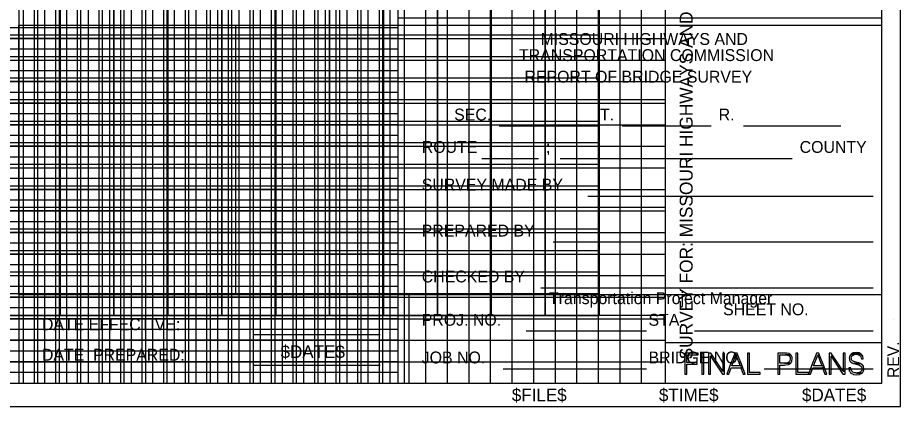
# Model space of a CAD drawing. Extents: x 0 to 31.6, y 0 to 20.8.
# Drawn here: x 23.41 to 31.6, y 0 to 3.61 of the extents above; entities that cross this region are included whole.
import ezdxf

# ---------------------------------------------------------------- set-up
doc = ezdxf.new("R2010")
doc.units = 0
for name, color, linetype in [('Border-Border', 7, 'Continuous'), ('Border-Bridge survey title block', 7, 'Continuous'), ('Border-Bridge xsection major grid lines', 7, 'Continuous'), ('Border-Bridge xsection minor grid lines', 7, 'Continuous'), ('Border-Construction Final Plans Stamp', 7, 'Continuous'), ('Border-Date stamp', 7, 'Continuous'), ('Border-File stamp', 7, 'Continuous'), ('Border-Full plan shape', 7, 'Continuous'), ('Border-Full profile major grid lines', 7, 'Continuous'), ('Border-Full profile minor grid lines', 7, 'Continuous'), ('Border-Full profile shape', 7, 'Continuous'), ('Border-Full xsection major grid lines', 7, 'Continuous'), ('Border-Full xsection minor grid lines', 7, 'Continuous'), ('Border-Plan bottom shape', 7, 'Continuous'), ('Border-Plan-profile major grid lines', 7, 'Continuous'), ('Border-Plan-profile minor grid lines', 7, 'Continuous'), ('Border-Plotting block', 7, 'Continuous'), ('Border-Profile bottom shape', 7, 'Continuous'), ('Border-Revision note', 7, 'Continuous'), ('Border-Time stamp', 7, 'Continuous'), ('Border-Title block - Final Plans Consultant Manual Seal', 7, 'Continuous'), ('Border-Title block - Final Plans Electronic Seal', 7, 'Continuous'), ('Border-Title block - Location Survey Electronic Seal', 7, 'Continuous'), ('Border-Title block - Standard Plans Electronic Seal', 7, 'Continuous'), ('Border-Xsection shape', 7, 'Continuous')]:
    doc.layers.add(name, color=color, linetype=linetype)

msp = doc.modelspace()

# ---------------------------------------------------------------- linework, layer by layer
at = {"layer": 'Border-Border'}
for p, q in [((31.425, 20.5875), (31.425, 0.2125)), ((31.425, 0.2125), (0.175, 0.2125)), ((31.5999, 0), (31.5999, 0))]:
    msp.add_line(p, q, dxfattribs=at)
at = {"layer": 'Border-Bridge survey title block'}
for p, q in [((26.9414, 3.6031), (31.4249, 3.6031)), ((27.8783, 2.6015), (28.7934, 2.6015)), ((29.02, 2.6015), (29.8454, 2.6015)), ((30.1465, 2.6015), (31.047, 2.6015)), ((27.7184, 2.3007), (28.2439, 2.3007)), ((28.4439, 2.3007), (30.5966, 2.3007)), ((28.7003, 1.9511), (31.3478, 1.9511)), ((28.3806, 1.5251), (31.3478, 1.5251)), ((28.2664, 1.0991), (31.3478, 1.0991)), ((28.1294, 0.6991), (29.2454, 0.6991)), ((29.6898, 0.6991), (31.3478, 0.6991)), ((27.9164, 0.3479), (29.2454, 0.3479)), ((30.3368, 0.3479), (31.3478, 0.3479))]:
    msp.add_line(p, q, dxfattribs=at)
msp.add_lwpolyline([(26.9414, 0.2125), (26.9414, 4.2047), (31.4249, 4.2047)], dxfattribs=at)
at = {"layer": 'Border-Bridge xsection major grid lines'}
for p, q in [((23.665, 0.2125), (23.665, 20.5875)), ((24.665, 0.2125), (24.665, 20.5875)), ((25.6649, 0.2125), (25.6649, 20.5875)), ((26.6649, 0.2125), (26.6649, 20.5875)), ((0.175, 3.2125), (26.9415, 3.2125)), ((0.175, 2.2125), (26.9415, 2.2125)), ((0.175, 1.2125), (26.9415, 1.2125))]:
    msp.add_line(p, q, dxfattribs=at)
at = {"layer": 'Border-Bridge xsection minor grid lines'}
for p, q in [((23.465, 20.5875), (23.465, 0.2125)), ((23.565, 20.5875), (23.565, 0.2125)), ((23.765, 20.5875), (23.765, 0.2125)), ((23.865, 20.5875), (23.865, 0.2125)), ((23.965, 20.5875), (23.965, 0.2125)), ((24.065, 20.5875), (24.065, 0.2125)), ((24.165, 20.5875), (24.165, 0.2125)), ((24.265, 20.5875), (24.265, 0.2125)), ((24.365, 20.5875), (24.365, 0.2125)), ((24.465, 20.5875), (24.465, 0.2125)), ((24.565, 20.5875), (24.565, 0.2125)), ((24.765, 20.5875), (24.765, 0.2125)), ((24.865, 20.5875), (24.865, 0.2125)), ((24.965, 20.5875), (24.965, 0.2125)), ((25.0649, 20.5875), (25.0649, 0.2125)), ((25.1649, 20.5875), (25.1649, 0.2125)), ((25.2649, 20.5875), (25.2649, 0.2125)), ((25.3649, 20.5875), (25.3649, 0.2125)), ((25.4649, 20.5875), (25.4649, 0.2125)), ((25.5649, 20.5875), (25.5649, 0.2125)), ((25.7649, 20.5875), (25.7649, 0.2125)), ((25.8649, 20.5875), (25.8649, 0.2125)), ((25.9649, 20.5875), (25.9649, 0.2125)), ((26.0649, 20.5875), (26.0649, 0.2125)), ((26.1649, 20.5875), (26.1649, 0.2125)), ((26.2649, 20.5875), (26.2649, 0.2125)), ((26.3649, 20.5875), (26.3649, 0.2125)), ((26.4649, 20.5875), (26.4649, 0.2125)), ((26.5649, 20.5875), (26.5649, 0.2125)), ((26.7649, 20.5875), (26.7649, 0.2125)), ((26.8649, 20.5875), (26.8649, 0.2125)), ((26.9415, 3.5125), (0.175, 3.5125)), ((26.9415, 3.4125), (0.175, 3.4125)), ((26.9415, 3.3125), (0.175, 3.3125)), ((26.9415, 3.1125), (0.175, 3.1125)), ((26.9415, 3.0125), (0.175, 3.0125)), ((26.9415, 2.9125), (0.175, 2.9125)), ((26.9415, 2.8125), (0.175, 2.8125)), ((26.9415, 2.7125), (0.175, 2.7125)), ((26.9415, 2.6125), (0.175, 2.6125)), ((26.9415, 2.5125), (0.175, 2.5125)), ((26.9415, 2.4125), (0.175, 2.4125)), ((26.9415, 2.3125), (0.175, 2.3125)), ((26.9415, 2.1125), (0.175, 2.1125)), ((26.9415, 2.0125), (0.175, 2.0125)), ((26.9415, 1.9125), (0.175, 1.9125)), ((26.9415, 1.8125), (0.175, 1.8125)), ((26.9415, 1.7125), (0.175, 1.7125)), ((26.9415, 1.6125), (0.175, 1.6125)), ((26.9415, 1.5125), (0.175, 1.5125)), ((26.9415, 1.4125), (0.175, 1.4125)), ((26.9415, 1.3125), (0.175, 1.3125)), ((26.9415, 1.1125), (0.175, 1.1125)), ((26.9415, 1.0125), (0.175, 1.0125)), ((26.9415, 0.9125), (0.175, 0.9125)), ((26.9415, 0.8125), (0.175, 0.8125)), ((26.9415, 0.7125), (0.175, 0.7125)), ((26.9415, 0.6125), (0.175, 0.6125)), ((26.9415, 0.5125), (0.175, 0.5125)), ((26.9415, 0.4125), (0.175, 0.4125)), ((26.9415, 0.3125), (0.175, 0.3125))]:
    msp.add_line(p, q, dxfattribs=at)
at = {"layer": 'Border-Construction Final Plans Stamp'}
msp.add_line((29.4171, 0.5925), (31.4249, 0.5925), dxfattribs=at)
for points in [[(29.6017, 0.3913), (29.6017, 0.2983), (29.6199, 0.2983), (29.6199, 0.3913), (29.716, 0.3913), (29.716, 0.4074), (29.6199, 0.4074), (29.6199, 0.4783), (29.7258, 0.4783), (29.7258, 0.4943), (29.6017, 0.4943), (29.6017, 0.4783), (29.6017, 0.4074)], [(29.758, 0.4943), (29.758, 0.2983), (29.7765, 0.2983), (29.7765, 0.4943)], [(29.8215, 0.3262), (29.8215, 0.2983), (29.8392, 0.2983), (29.8392, 0.3262), (29.8392, 0.4665), (29.8596, 0.4665), (29.8414, 0.4943), (29.8215, 0.4943), (29.8215, 0.4665)], [(29.952, 0.4943), (29.952, 0.3262), (29.9697, 0.3262), (29.9697, 0.4943)], [(30.0132, 0.3587), (29.9903, 0.2983), (30.009, 0.2983), (30.0315, 0.3587), (30.1377, 0.3587), (30.1317, 0.3744), (30.0373, 0.3744), (30.0754, 0.4754), (30.0933, 0.4754), (30.0862, 0.4943), (30.0647, 0.4943), (30.0575, 0.4754), (30.0192, 0.3744)], [(30.1813, 0.3143), (30.1813, 0.2983), (30.3, 0.2983), (30.3, 0.3143), (30.1998, 0.3143), (30.1998, 0.4943), (30.1813, 0.4943)], [(30.4647, 0.3834), (30.4647, 0.2983), (30.4828, 0.2983), (30.4828, 0.3834), (30.5245, 0.3834), (30.5391, 0.3839), (30.5619, 0.3879), (30.5812, 0.3987), (30.582, 0.3998), (30.4828, 0.3998), (30.4828, 0.3999), (30.4828, 0.4015), (30.4828, 0.4086), (30.4828, 0.4168), (30.4828, 0.4228), (30.4828, 0.4394), (30.4828, 0.4396), (30.4828, 0.4557), (30.4828, 0.4598), (30.4828, 0.4682), (30.4828, 0.4757), (30.4828, 0.4774), (30.4828, 0.4779), (30.4828, 0.4783), (30.5834, 0.4783), (30.5671, 0.4893), (30.5474, 0.4937), (30.5333, 0.4943), (30.4647, 0.4943), (30.4647, 0.4937), (30.4647, 0.4893), (30.4647, 0.4783), (30.4647, 0.4779), (30.4647, 0.4774), (30.4647, 0.4757), (30.4647, 0.4682), (30.4647, 0.4598), (30.4647, 0.4557), (30.4647, 0.4396), (30.4647, 0.4394), (30.4647, 0.4228), (30.4647, 0.4168), (30.4647, 0.4086), (30.4647, 0.4015), (30.4647, 0.3999), (30.4647, 0.3998), (30.4647, 0.3987), (30.4647, 0.3879), (30.4647, 0.3839)], [(30.6295, 0.3143), (30.6295, 0.2983), (30.7482, 0.2983), (30.7482, 0.3143), (30.648, 0.3143), (30.648, 0.4943), (30.6295, 0.4943)], [(30.7711, 0.3587), (30.7482, 0.2983), (30.7669, 0.2983), (30.7894, 0.3587), (30.8956, 0.3587), (30.8896, 0.3744), (30.7952, 0.3744), (30.8333, 0.4754), (30.8512, 0.4754), (30.8441, 0.4943), (30.8226, 0.4943), (30.8154, 0.4754), (30.7771, 0.3744)], [(30.9392, 0.3262), (30.9392, 0.2983), (30.9569, 0.2983), (30.9569, 0.3262), (30.9569, 0.4665), (30.9774, 0.4665), (30.9591, 0.4943), (30.9392, 0.4943), (30.9392, 0.4665)], [(31.0697, 0.4943), (31.0697, 0.3262), (31.0874, 0.3262), (31.0874, 0.4943)], [(31.1443, 0.4851), (31.1434, 0.4846), (31.2378, 0.4846), (31.2374, 0.4851), (31.2175, 0.4957), (31.2149, 0.4961), (31.1643, 0.4961), (31.1636, 0.4957)], [(31.1906, 0.4997), (31.1643, 0.4961), (31.2149, 0.4961)], [(29.9314, 0.3262), (29.9498, 0.2983), (29.9697, 0.2983), (29.9697, 0.3262), (29.952, 0.3262), (29.8597, 0.4665), (29.8392, 0.4665)], [(30.0754, 0.4754), (30.1135, 0.3744), (30.1317, 0.3744), (30.0934, 0.4754)], [(30.5324, 0.4783), (30.5394, 0.4779), (30.5839, 0.4779), (30.5834, 0.4783)], [(30.5657, 0.4086), (30.5497, 0.4015), (30.5831, 0.4015), (30.588, 0.4086), (30.5936, 0.4168), (30.5947, 0.4228), (30.5946, 0.4228), (30.5976, 0.4394), (30.5976, 0.4396), (30.5954, 0.4557), (30.5949, 0.4598), (30.59, 0.4682), (30.5856, 0.4757), (30.5846, 0.4774), (30.5839, 0.4779), (30.5394, 0.4779), (30.5428, 0.4774), (30.5544, 0.4757), (30.5686, 0.4682), (30.5741, 0.4598), (30.5767, 0.4557), (30.5791, 0.4396), (30.5791, 0.4394), (30.5762, 0.4228), (30.5718, 0.4168)], [(30.8333, 0.4754), (30.8714, 0.3744), (30.8896, 0.3744), (30.8513, 0.4754)], [(31.0492, 0.3262), (31.0675, 0.2983), (31.0874, 0.2983), (31.0874, 0.3262), (31.0697, 0.3262), (30.9774, 0.4665), (30.9569, 0.4665)], [(31.1654, 0.3978), (31.1677, 0.3969), (31.2311, 0.3969), (31.2296, 0.3978), (31.2145, 0.4031), (31.2144, 0.4031), (31.2128, 0.4037), (31.2007, 0.4071), (31.1779, 0.4129), (31.1752, 0.4137), (31.1671, 0.4161), (31.1548, 0.4228), (31.1503, 0.4286), (31.1471, 0.4328), (31.1457, 0.4397), (31.1445, 0.4462), (31.1445, 0.4464), (31.1445, 0.4469), (31.1446, 0.4474), (31.1467, 0.4596), (31.1469, 0.4611), (31.151, 0.4668), (31.1515, 0.4674), (31.1515, 0.4674), (31.1551, 0.4724), (31.1555, 0.473), (31.1703, 0.481), (31.1709, 0.4814), (31.1897, 0.4836), (31.2385, 0.4836), (31.2378, 0.4846), (31.1434, 0.4846), (31.1427, 0.4836), (31.141, 0.4814), (31.1408, 0.481), (31.135, 0.473), (31.1346, 0.4724), (31.1309, 0.4674), (31.1305, 0.4668), (31.1294, 0.4611), (31.1291, 0.4596), (31.1267, 0.4474), (31.1266, 0.4469), (31.1267, 0.4464), (31.1267, 0.4462), (31.1276, 0.4397), (31.1286, 0.4328), (31.1292, 0.4286), (31.1325, 0.4228), (31.1365, 0.4161), (31.1379, 0.4137), (31.139, 0.4129), (31.1464, 0.4071), (31.1508, 0.4037), (31.1515, 0.4031)], [(31.238, 0.4462), (31.2384, 0.4397), (31.2565, 0.4397), (31.2561, 0.4462), (31.2561, 0.4464), (31.2561, 0.4469), (31.2561, 0.4474), (31.2528, 0.4596), (31.2528, 0.4596), (31.2524, 0.4611), (31.2509, 0.4668), (31.2507, 0.4674), (31.2469, 0.4724), (31.2465, 0.473), (31.2404, 0.481), (31.2402, 0.4814), (31.2402, 0.4814), (31.2385, 0.4836), (31.1897, 0.4836), (31.2063, 0.4814), (31.2086, 0.481), (31.2239, 0.473), (31.225, 0.4724), (31.2287, 0.4674), (31.2291, 0.4668), (31.2332, 0.4611), (31.2343, 0.4596), (31.2377, 0.4474), (31.2378, 0.4469), (31.2379, 0.4464)], [(30.1194, 0.3587), (30.1418, 0.2983), (30.1606, 0.2983), (30.1377, 0.3587)], [(30.5323, 0.3999), (30.5248, 0.3998), (30.582, 0.3998), (30.582, 0.3999)], [(30.5496, 0.4015), (30.5324, 0.3999), (30.582, 0.3999), (30.5831, 0.4015)], [(30.8772, 0.3587), (30.8997, 0.2983), (30.9185, 0.2983), (30.8956, 0.3587)], [(31.1647, 0.2968), (31.1947, 0.293), (31.2202, 0.2968), (31.224, 0.2974), (31.2444, 0.309), (31.195, 0.309), (31.1924, 0.3093), (31.186, 0.3101), (31.1753, 0.3113), (31.174, 0.3119), (31.1585, 0.3186), (31.1553, 0.3221), (31.1498, 0.3279), (31.1498, 0.3279), (31.1471, 0.3308), (31.1459, 0.3322), (31.1442, 0.337), (31.1408, 0.3468), (31.1404, 0.3502), (31.1403, 0.3517), (31.1398, 0.3577), (31.1217, 0.3577), (31.1219, 0.3517), (31.122, 0.3502), (31.1227, 0.3468), (31.1246, 0.337), (31.1255, 0.3322), (31.1258, 0.3308), (31.1278, 0.3279), (31.1319, 0.3221), (31.1343, 0.3186), (31.139, 0.3119), (31.1395, 0.3113), (31.1403, 0.3101), (31.1409, 0.3093), (31.1415, 0.309), (31.1636, 0.2974)], [(31.1974, 0.3093), (31.195, 0.309), (31.2444, 0.309), (31.2449, 0.3093), (31.2462, 0.3101), (31.2471, 0.3113), (31.2475, 0.3119), (31.2521, 0.3186), (31.2545, 0.3221), (31.2585, 0.3279), (31.2589, 0.3308), (31.2589, 0.3308), (31.2591, 0.3322), (31.2598, 0.337), (31.2613, 0.3468), (31.2618, 0.3502), (31.2621, 0.3517), (31.2592, 0.3661), (31.2579, 0.3723), (31.2541, 0.3771), (31.2484, 0.3846), (31.2458, 0.3879), (31.2439, 0.3891), (31.2439, 0.3891), (31.2361, 0.3938), (31.2311, 0.3969), (31.1677, 0.3969), (31.1796, 0.3938), (31.1982, 0.3891), (31.2022, 0.3879), (31.2142, 0.3846), (31.2302, 0.3771), (31.2346, 0.3723), (31.2402, 0.3661), (31.2438, 0.3517), (31.2437, 0.3502), (31.2434, 0.3468), (31.2427, 0.337), (31.2399, 0.3322), (31.2391, 0.3308), (31.2374, 0.3279), (31.2341, 0.3221), (31.2281, 0.3186), (31.2166, 0.3119), (31.2124, 0.3113), (31.203, 0.3101)]]:
    msp.add_lwpolyline(points, close=True, dxfattribs=at)
at = {"layer": 'Border-Full plan shape'}
msp.add_lwpolyline([(0.8061, 19.9564), (28.8061, 19.9564), (28.8061, 0.8436), (0.8061, 0.8436)], close=True, dxfattribs=at)
at = {"layer": 'Border-Full profile major grid lines'}
for p, q in [((23.8061, 19.8436), (23.8061, 0.8436)), ((24.8061, 19.8436), (24.8061, 0.8436)), ((25.8061, 19.8436), (25.8061, 0.8436)), ((26.8061, 19.8436), (26.8061, 0.8436)), ((27.8061, 19.8436), (27.8061, 0.8436)), ((28.8061, 19.8436), (28.8061, 0.8436)), ((29.4171, 2.8436), (0.175, 2.8436)), ((29.4171, 1.8436), (0.175, 1.8436)), ((29.4171, 0.8436), (0.175, 0.8436))]:
    msp.add_line(p, q, dxfattribs=at)
at = {"layer": 'Border-Full profile minor grid lines'}
for p, q in [((24.3061, 19.8436), (24.3061, 0.8436)), ((25.3061, 19.8436), (25.3061, 0.8436)), ((26.3061, 19.8436), (26.3061, 0.8436)), ((27.3061, 19.8436), (27.3061, 0.8436)), ((28.3061, 19.8436), (28.3061, 0.8436)), ((28.8061, 3.4436), (0.8061, 3.4436)), ((28.8061, 3.2436), (0.8061, 3.2436)), ((28.8061, 3.0436), (0.8061, 3.0436)), ((28.8061, 2.6436), (0.8061, 2.6436)), ((28.8061, 2.4436), (0.8061, 2.4436)), ((28.8061, 2.2436), (0.8061, 2.2436)), ((28.8061, 2.0436), (0.8061, 2.0436)), ((28.8061, 1.6436), (0.8061, 1.6436)), ((28.8061, 1.4436), (0.8061, 1.4436)), ((28.8061, 1.2436), (0.8061, 1.2436)), ((28.8061, 1.0436), (0.8061, 1.0436))]:
    msp.add_line(p, q, dxfattribs=at)
at = {"layer": 'Border-Full profile shape'}
msp.add_lwpolyline([(0.8061, 19.9564), (28.8061, 19.9564), (28.8061, 0.8436), (0.8061, 0.8436)], close=True, dxfattribs=at)
at = {"layer": 'Border-Full xsection major grid lines'}
for p, q in [((23.8, 0.2125), (23.8, 20.5875)), ((24.8, 0.2125), (24.8, 20.5875)), ((25.7999, 0.2125), (25.7999, 20.5875)), ((26.7999, 0.2125), (26.7999, 20.5875)), ((27.7999, 0.2125), (27.7999, 20.5875)), ((28.7999, 0.2125), (28.7999, 20.5875)), ((0.175, 3.2125), (29.4171, 3.2125)), ((0.175, 2.2125), (29.4171, 2.2125)), ((0.175, 1.2125), (29.4171, 1.2125))]:
    msp.add_line(p, q, dxfattribs=at)
at = {"layer": 'Border-Full xsection minor grid lines'}
for p, q in [((23.6, 0.2125), (23.6, 20.5875)), ((24, 0.2125), (24, 20.5875)), ((24.2, 0.2125), (24.2, 20.5875)), ((24.4, 0.2125), (24.4, 20.5875)), ((24.6, 0.2125), (24.6, 20.5875)), ((24.9999, 0.2125), (24.9999, 20.5875)), ((25.1999, 0.2125), (25.1999, 20.5875)), ((25.3999, 0.2125), (25.3999, 20.5875)), ((25.5999, 0.2125), (25.5999, 20.5875)), ((25.9999, 0.2125), (25.9999, 20.5875)), ((26.1999, 0.2125), (26.1999, 20.5875)), ((26.3999, 0.2125), (26.3999, 20.5875)), ((26.5999, 0.2125), (26.5999, 20.5875)), ((26.9999, 0.2125), (26.9999, 20.5875)), ((27.1999, 0.2125), (27.1999, 20.5875)), ((27.3999, 0.2125), (27.3999, 20.5875)), ((27.5999, 0.2125), (27.5999, 20.5875)), ((27.9999, 0.2125), (27.9999, 20.5875)), ((28.1999, 0.2125), (28.1999, 20.5875)), ((28.3999, 0.2125), (28.3999, 20.5875)), ((28.5999, 0.2125), (28.5999, 20.5875)), ((28.9999, 0.2125), (28.9999, 20.5875)), ((29.1999, 0.2125), (29.1999, 20.5875)), ((0.175, 3.4125), (29.4171, 3.4125)), ((0.175, 3.0125), (29.4171, 3.0125)), ((0.175, 2.8125), (29.4171, 2.8125)), ((0.175, 2.6125), (29.4171, 2.6125)), ((0.175, 2.4125), (29.4171, 2.4125)), ((0.175, 2.0125), (29.4171, 2.0125)), ((0.175, 1.8125), (29.4171, 1.8125)), ((0.175, 1.6125), (29.4171, 1.6125)), ((0.175, 1.4125), (29.4171, 1.4125)), ((0.175, 1.0125), (29.4171, 1.0125)), ((0.175, 0.8125), (29.4171, 0.8125)), ((0.175, 0.6125), (29.4171, 0.6125)), ((0.175, 0.4125), (29.4171, 0.4125))]:
    msp.add_line(p, q, dxfattribs=at)
at = {"layer": 'Border-Plan bottom shape'}
msp.add_lwpolyline([(0.8061, 10.3253), (28.8061, 10.3253), (28.8061, 0.8436), (0.8061, 0.8436)], close=True, dxfattribs=at)
at = {"layer": 'Border-Plan-profile major grid lines'}
for p, q in [((23.8061, 0.8436), (23.8061, 9.8436)), ((24.8061, 0.8436), (24.8061, 9.8436)), ((25.8061, 0.8436), (25.8061, 9.8436)), ((26.8061, 0.8436), (26.8061, 9.8436)), ((27.8061, 0.8436), (27.8061, 9.8436)), ((28.8061, 0.8436), (28.8061, 9.8436)), ((29.4233, 2.8436), (0.1811, 2.8436)), ((29.4233, 1.8436), (0.1811, 1.8436)), ((29.4233, 0.8436), (0.1811, 0.8436))]:
    msp.add_line(p, q, dxfattribs=at)
at = {"layer": 'Border-Plan-profile minor grid lines'}
for p, q in [((24.3061, 0.8436), (24.3061, 9.8436)), ((25.3061, 0.8436), (25.3061, 9.8436)), ((26.3061, 0.8436), (26.3061, 9.8436)), ((27.3061, 0.8436), (27.3061, 9.8436)), ((28.3061, 0.8436), (28.3061, 9.8436)), ((28.8061, 3.4436), (0.8061, 3.4436)), ((28.8061, 3.2436), (0.8061, 3.2436)), ((28.8061, 3.0436), (0.8061, 3.0436)), ((28.8061, 2.6436), (0.8061, 2.6436)), ((28.8061, 2.4436), (0.8061, 2.4436)), ((28.8061, 2.2436), (0.8061, 2.2436)), ((28.8061, 2.0436), (0.8061, 2.0436)), ((28.8061, 1.6436), (0.8061, 1.6436)), ((28.8061, 1.4436), (0.8061, 1.4436)), ((28.8061, 1.2436), (0.8061, 1.2436)), ((28.8061, 1.0436), (0.8061, 1.0436))]:
    msp.add_line(p, q, dxfattribs=at)
at = {"layer": 'Border-Plotting block'}
msp.add_lwpolyline([(0, 0), (31.5999, 0), (31.5999, 20.8), (0, 20.8)], close=True, dxfattribs=at)
at = {"layer": 'Border-Profile bottom shape'}
msp.add_lwpolyline([(0.8061, 0.8436), (28.8061, 0.8436), (28.8061, 9.8436), (0.8061, 9.8436)], close=True, dxfattribs=at)
at = {"layer": 'Border-Revision note'}
msp.add_line((31.5347, 0.8092), (31.5347, 0.8092), dxfattribs=at)
at = {"layer": 'Border-Title block - Final Plans Consultant Manual Seal'}
msp.add_line((29.4171, 20.5875), (29.4171, 0.2125), dxfattribs=at)
at = {"layer": 'Border-Title block - Final Plans Electronic Seal'}
msp.add_line((29.4171, 20.5875), (29.4171, 0.2125), dxfattribs=at)
at = {"layer": 'Border-Title block - Location Survey Electronic Seal'}
msp.add_line((29.4171, 20.5875), (29.4171, 0.2125), dxfattribs=at)
at = {"layer": 'Border-Title block - Standard Plans Electronic Seal'}
for p, q in [((23.4249, 4.8718), (23.4249, 0.2125)), ((23.4249, 3.5375), (31.425, 3.5375)), ((25.4328, 3.5375), (25.4328, 1.0375)), ((23.4249, 1.0375), (31.425, 1.0375)), ((27.0397, 1.0375), (27.0397, 0.2125)), ((29.4171, 1.0375), (29.4171, 0.2125)), ((25.6068, 0.6651), (26.7737, 0.6651)), ((25.6068, 0.3818), (26.7737, 0.3818))]:
    msp.add_line(p, q, dxfattribs=at)
msp.add_lwpolyline([(23.4249, 3.5375), (25.4328, 3.5375), (25.4328, 1.0375), (23.4249, 1.0375)], close=True, dxfattribs=at)
at = {"layer": 'Border-Xsection shape'}
msp.add_lwpolyline([(29.4171, 0.2125), (0.175, 0.2125), (0.175, 20.5875), (29.4171, 20.5875)], close=True, dxfattribs=at)

# ---------------------------------------------------------------- texts
at = {"layer": 'Border-Bridge survey title block'}
for s, height, p in [('MISSOURI HIGHWAYS AND', 0.110166, (28.2628, 3.3527)), ('TRANSPORTATION COMMISSION', 0.110192, (28.0628, 3.2031)), ('REPORT OF BRIDGE SURVEY', 0.110192, (28.1131, 3.0031)), ('SEC.', 0.11019, (27.4612, 2.6518)), ('T.', 0.11019, (28.8139, 2.6518)), ('R.', 0.11019, (29.9147, 2.6518)), ('ROUTE', 0.11019, (27.1604, 2.3511)), ('COUNTY', 0.11019, (30.6659, 2.3511)), (';', 0.1102, (28.3131, 2.3511)), ('SURVEY MADE BY', 0.110192, (27.1604, 2.0015)), ('PREPARED BY', 0.110166, (27.1604, 1.5755)), ('CHECKED BY', 0.11019, (27.1604, 1.1495)), ('Transportation Project Manager', 0.110166, (28.3409, 0.948)), ('PROJ. NO.', 0.11019, (27.1604, 0.7479)), ('STA.', 0.11019, (29.2643, 0.7479)), ('JOB NO.', 0.11019, (27.1604, 0.3983)), ('BRIDGE NO.', 0.11019, (29.2643, 0.3983))]:
    msp.add_text(s, height=height, dxfattribs=at).set_placement(p)
at = {"layer": 'Border-Date stamp'}
msp.add_text('$DATE$', height=0.11811, dxfattribs=at).set_placement((30.6876, 0.0472))
at = {"layer": 'Border-File stamp'}
msp.add_text('$FILE$', height=0.11811, dxfattribs=at).set_placement((27.9962, 0.0472))
at = {"layer": 'Border-Revision note'}
msp.add_text('REV.', height=0.10827, rotation=90, dxfattribs=at).set_placement((31.5888, 0.263))
at = {"layer": 'Border-Time stamp'}
msp.add_text('$TIME$', height=0.11811, dxfattribs=at).set_placement((29.3609, 0.0472))
at = {"layer": 'Border-Title block - Location Survey Electronic Seal'}
msp.add_text('SURVEY FOR: MISSOURI HIGHWAYS AND TRANSPORTATION COMMISSION', height=0.12, rotation=90, dxfattribs=at).set_placement((29.6734, 0.4356))
at = {"layer": 'Border-Title block - Standard Plans Electronic Seal'}
for s, height, p in [('SHEET NO.', 0.11, (29.9561, 0.845)), ('DATE EFFECTIVE:', 0.11, (23.6381, 0.7063)), ('$DATE$', 0.11811, (25.8509, 0.4474)), ('DATE  PREPARED:', 0.11, (23.6381, 0.4237))]:
    msp.add_text(s, height=height, dxfattribs=at).set_placement(p)

doc.saveas('drawing.dxf')
